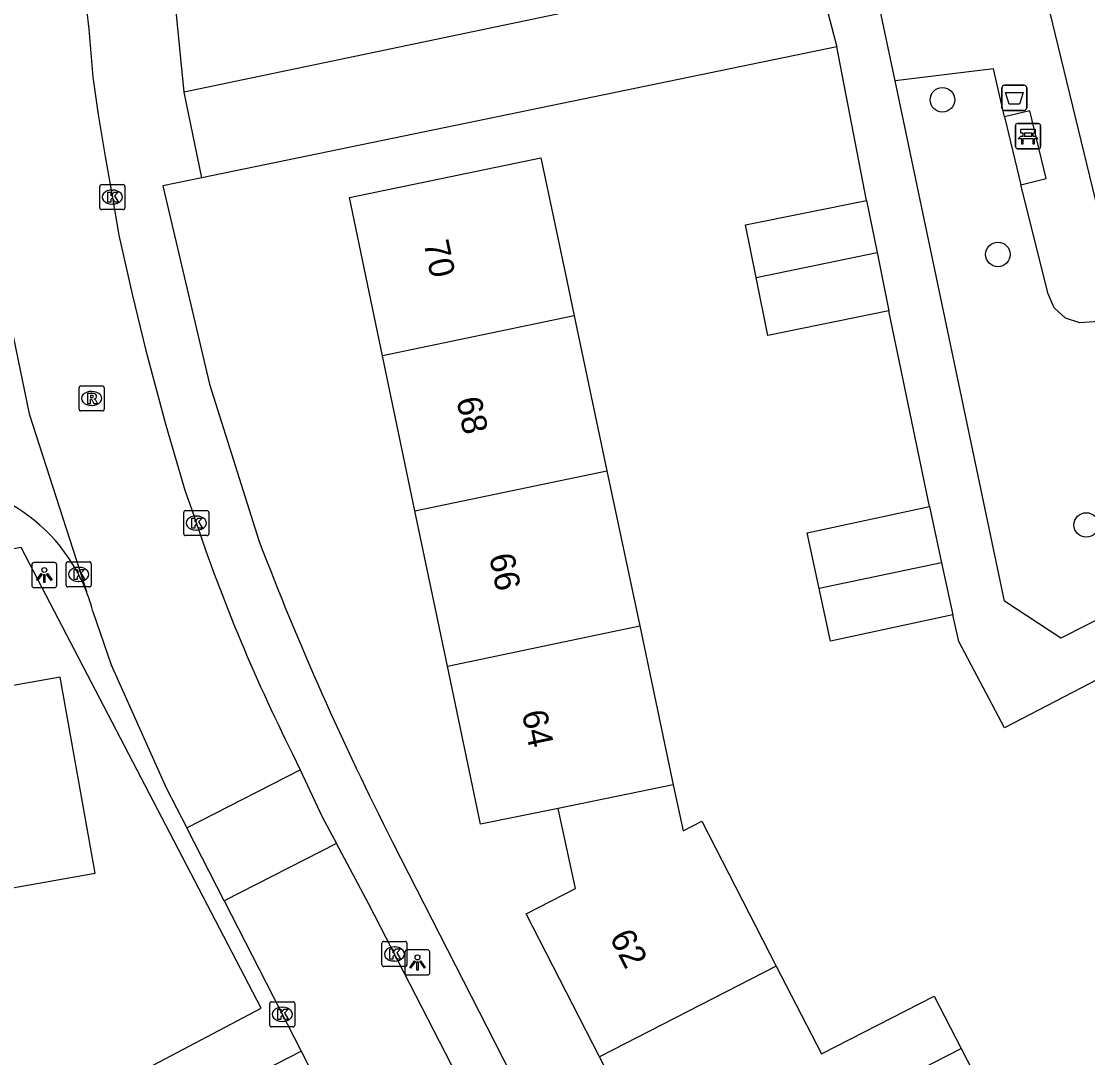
# Model space of a CAD drawing. Extents: x 158461 to 159795, y 387220 to 388672.
# Drawn here: x 159150.7 to 159193.22, y 387884.38 to 387925.7 of the extents above; entities that cross this region are included whole.
import ezdxf

# ---------------------------------------------------------------- set-up
doc = ezdxf.new("R2010")
doc.units = 0
for name, color, linetype in [('IMGEO_Afvalbak', 7, 'Continuous'), ('IMGEO_Bank', 7, 'Continuous'), ('IMGEO_Boom', 7, 'Continuous'), ('IMGEO_Groenvoorziening', 7, 'Continuous'), ('IMGEO_Kolk', 7, 'Continuous'), ('IMGEO_Lichtpunt', 7, 'Continuous'), ('IMGEO_Pand', 7, 'Continuous'), ('IMGEO_Pand_nummerreeks', 7, 'Continuous'), ('IMGEO_Rijbaan_lokaal_open', 7, 'Continuous'), ('IMGEO_Rioolput', 7, 'Continuous'), ('IMGEO_Voetpad_open', 7, 'Continuous')]:
    doc.layers.add(name, color=color, linetype=linetype)

msp = doc.modelspace()

# ---------------------------------------------------------------- linework, layer by layer
at = {"layer": 'IMGEO_Afvalbak'}
for p, q in [((159189.796, 387922.249), (159189.796, 387923.049)), ((159189.796, 387923.049), (159189.796, 387922.249)), ((159189.896, 387923.149), (159190.686, 387923.149)), ((159190.686, 387923.149), (159189.896, 387923.149)), ((159190.786, 387923.049), (159190.786, 387922.249)), ((159190.786, 387922.249), (159190.786, 387923.049)), ((159190.686, 387922.149), (159189.896, 387922.149)), ((159189.896, 387922.149), (159190.686, 387922.149))]:
    msp.add_line(p, q, dxfattribs=at)
msp.add_lwpolyline([(159189.939, 387922.863), (159190.643, 387922.863), (159190.494, 387922.393), (159190.088, 387922.393), (159189.939, 387922.863)], dxfattribs=at)
for centre, start, end in [((159189.896, 387923.049), 90, 180), ((159189.896, 387923.049), 90, 180), ((159190.686, 387923.049), 0, 90), ((159190.686, 387923.049), 360, 90), ((159189.896, 387922.249), 180, 270), ((159189.896, 387922.249), 180, 270), ((159190.686, 387922.249), 270, 0), ((159190.686, 387922.249), 270, 0)]:
    msp.add_arc(centre, 0.1, start, end, dxfattribs=at)
at = {"layer": 'IMGEO_Bank'}
for p, q in [((159190.338, 387920.697), (159190.338, 387921.538)), ((159190.338, 387921.538), (159190.338, 387920.697)), ((159190.413, 387921.622), (159191.254, 387921.622)), ((159191.254, 387921.622), (159190.413, 387921.622)), ((159191.338, 387921.547), (159191.338, 387920.706)), ((159191.338, 387920.706), (159191.338, 387921.547)), ((159190.647, 387921.128), (159190.647, 387921.234)), ((159190.691, 387921.234), (159190.691, 387921.128)), ((159190.979, 387921.24), (159190.697, 387921.24)), ((159190.697, 387921.122), (159190.979, 387921.122)), ((159190.985, 387921.128), (159190.985, 387921.234)), ((159191.029, 387921.234), (159191.029, 387921.128)), ((159191.035, 387921.02), (159190.642, 387921.02)), ((159191.263, 387920.622), (159190.422, 387920.622)), ((159190.422, 387920.622), (159191.263, 387920.622))]:
    msp.add_line(p, q, dxfattribs=at)
for points in [[(159190.585, 387921.02), (159190.443, 387921.02), (159190.555, 387921.122), (159190.641, 387921.122)], [(159190.641, 387921.24), (159190.555, 387921.24), (159190.555, 387921.401), (159191.118, 387921.401), (159191.118, 387921.24), (159191.035, 387921.24)], [(159191.035, 387921.122), (159191.118, 387921.122), (159191.23, 387921.02), (159191.091, 387921.02)], [(159190.635, 387921.013), (159190.635, 387920.806), (159190.592, 387920.806), (159190.592, 387921.013)], [(159191.085, 387921.013), (159191.085, 387920.806), (159191.041, 387920.806), (159191.041, 387921.013)]]:
    msp.add_lwpolyline(points, dxfattribs=at)
for centre, radius, start, end in [((159190.416, 387921.544), 0.0779, 92.4484, 184.2845), ((159190.416, 387921.544), 0.0779, 92.4484, 184.2845), ((159191.26, 387921.544), 0.0779, 2.4484, 94.2845), ((159191.26, 387921.544), 0.0779, 2.4484, 94.2845), ((159190.64, 387921.233), 0.00671, 2.8957, 87.1043), ((159190.64, 387921.129), 0.00671, 272.8957, 357.1043), ((159190.697, 387921.233), 0.00671, 92.8957, 177.1043), ((159190.697, 387921.129), 0.00671, 182.8957, 267.1043), ((159190.979, 387921.233), 0.00671, 2.8957, 87.1043), ((159190.979, 387921.129), 0.00671, 272.8957, 357.1043), ((159191.036, 387921.233), 0.00671, 92.8957, 177.1043), ((159191.036, 387921.129), 0.00671, 182.8957, 267.1043), ((159190.416, 387920.7), 0.0779, 182.4484, 274.2845), ((159190.416, 387920.7), 0.0779, 182.4484, 274.2845), ((159190.585, 387921.013), 0.00671, 2.8957, 87.1043), ((159190.642, 387921.013), 0.00671, 92.8957, 177.1043), ((159191.034, 387921.013), 0.00671, 2.8957, 87.1043), ((159191.091, 387921.013), 0.00671, 92.8957, 177.1043), ((159191.26, 387920.7), 0.0779, 272.4484, 4.2845), ((159191.26, 387920.7), 0.0779, 272.4484, 4.2845)]:
    msp.add_arc(centre, radius, start, end, dxfattribs=at)
at = {"layer": 'IMGEO_Boom'}
for centre in [(159187.425, 387922.57), (159189.638, 387916.405), (159193.159, 387905.619)]:
    msp.add_circle(centre, 0.489, dxfattribs=at)
at = {"layer": 'IMGEO_Groenvoorziening'}
for points in [[(159206.203, 387929.607), (159191.693, 387926.088), (159194.08, 387916.245), (159208.541, 387919.752), (159206.203, 387929.607)], [(159189.899, 387921.887), (159189.467, 387923.801), (159185.537, 387923.326)], [(159211.851, 387914.973), (159209.119, 387915.028), (159207.647, 387913.997), (159206.483, 387913.38), (159205.261, 387912.888), (159203.994, 387912.527), (159202.696, 387912.3), (159201.382, 387912.211), (159200.066, 387912.259), (159198.762, 387912.444), (159197.484, 387912.764), (159196.247, 387913.217), (159195.064, 387913.796), (159193.477, 387913.72), (159192.904, 387913.672), (159192.327, 387913.866), (159191.878, 387914.278), (159191.636, 387914.837), (159190.556, 387919.186)]]:
    msp.add_lwpolyline(points, dxfattribs=at)
at = {"layer": 'IMGEO_Kolk'}
for p, q in [((159153.83, 387918.267), (159153.83, 387919.119)), ((159153.905, 387919.193), (159154.757, 387919.193)), ((159154.831, 387919.119), (159154.831, 387918.267)), ((159154.318, 387918.973), (159154.343, 387918.973)), ((159154.757, 387918.193), (159153.905, 387918.193)), ((159154.341, 387918.413), (159154.316, 387918.413)), ((159157.175, 387905.268), (159157.175, 387906.12)), ((159157.25, 387906.194), (159158.102, 387906.194)), ((159157.663, 387905.974), (159157.688, 387905.974)), ((159158.176, 387906.12), (159158.176, 387905.268)), ((159157.686, 387905.414), (159157.661, 387905.414)), ((159158.102, 387905.194), (159157.25, 387905.194)), ((159152.559, 387904.15), (159153.411, 387904.15)), ((159152.484, 387903.224), (159152.484, 387904.076)), ((159152.972, 387903.93), (159152.997, 387903.93)), ((159153.485, 387904.076), (159153.485, 387903.224)), ((159152.995, 387903.37), (159152.97, 387903.37)), ((159153.411, 387903.15), (159152.559, 387903.15)), ((159165.075, 387888.088), (159165.075, 387888.94)), ((159165.15, 387889.014), (159166.002, 387889.014)), ((159166.076, 387888.94), (159166.076, 387888.088)), ((159165.563, 387888.794), (159165.588, 387888.794)), ((159166.002, 387888.014), (159165.15, 387888.014)), ((159165.586, 387888.234), (159165.561, 387888.234)), ((159160.605, 387885.682), (159160.605, 387886.534)), ((159160.68, 387886.608), (159161.532, 387886.608)), ((159161.093, 387886.388), (159161.118, 387886.388)), ((159161.606, 387886.534), (159161.606, 387885.682)), ((159161.116, 387885.828), (159161.091, 387885.828)), ((159161.532, 387885.608), (159160.68, 387885.608))]:
    msp.add_line(p, q, dxfattribs=at)
for points in [[(159153.83, 387918.267), (159153.83, 387919.119)], [(159153.905, 387919.193), (159154.757, 387919.193)], [(159154.831, 387919.119), (159154.831, 387918.267)], [(159154.151, 387918.893), (159154.274, 387918.893), (159154.274, 387918.742), (159154.404, 387918.893), (159154.568, 387918.893), (159154.422, 387918.742), (159154.575, 387918.493), (159154.423, 387918.493), (159154.338, 387918.657), (159154.274, 387918.59), (159154.274, 387918.493), (159154.151, 387918.493), (159154.151, 387918.893)], [(159154.757, 387918.193), (159153.905, 387918.193)], [(159157.175, 387905.268), (159157.175, 387906.12)], [(159157.25, 387906.194), (159158.102, 387906.194)], [(159157.496, 387905.894), (159157.619, 387905.894), (159157.619, 387905.743), (159157.749, 387905.894), (159157.913, 387905.894), (159157.767, 387905.743), (159157.92, 387905.494), (159157.768, 387905.494), (159157.683, 387905.658), (159157.619, 387905.591), (159157.619, 387905.494), (159157.496, 387905.494), (159157.496, 387905.894)], [(159158.176, 387906.12), (159158.176, 387905.268)], [(159158.102, 387905.194), (159157.25, 387905.194)], [(159152.559, 387904.15), (159153.411, 387904.15)], [(159152.484, 387903.224), (159152.484, 387904.076)], [(159152.805, 387903.85), (159152.928, 387903.85), (159152.928, 387903.699), (159153.058, 387903.85), (159153.222, 387903.85), (159153.076, 387903.699), (159153.229, 387903.45), (159153.077, 387903.45), (159152.992, 387903.614), (159152.928, 387903.547), (159152.928, 387903.45), (159152.805, 387903.45), (159152.805, 387903.85)], [(159153.485, 387904.076), (159153.485, 387903.224)], [(159153.411, 387903.15), (159152.559, 387903.15)], [(159165.075, 387888.088), (159165.075, 387888.94)], [(159165.15, 387889.014), (159166.002, 387889.014)], [(159166.076, 387888.94), (159166.076, 387888.088)], [(159165.396, 387888.714), (159165.519, 387888.714), (159165.519, 387888.563), (159165.649, 387888.714), (159165.813, 387888.714), (159165.667, 387888.563), (159165.82, 387888.314), (159165.668, 387888.314), (159165.583, 387888.478), (159165.519, 387888.411), (159165.519, 387888.314), (159165.396, 387888.314), (159165.396, 387888.714)], [(159166.002, 387888.014), (159165.15, 387888.014)], [(159160.605, 387885.682), (159160.605, 387886.534)], [(159160.68, 387886.608), (159161.532, 387886.608)], [(159160.926, 387886.308), (159161.049, 387886.308), (159161.049, 387886.157), (159161.179, 387886.308), (159161.343, 387886.308), (159161.197, 387886.157), (159161.35, 387885.908), (159161.198, 387885.908), (159161.113, 387886.072), (159161.049, 387886.005), (159161.049, 387885.908), (159160.926, 387885.908), (159160.926, 387886.308)], [(159161.606, 387886.534), (159161.606, 387885.682)], [(159161.532, 387885.608), (159160.68, 387885.608)]]:
    msp.add_lwpolyline(points, dxfattribs=at)
for centre, start, end in [((159153.907, 387919.117), 91.552, 178.448), ((159153.907, 387919.117), 91.552, 178.448), ((159154.755, 387919.117), 1.552, 88.448), ((159154.755, 387919.117), 1.552, 88.448), ((159153.907, 387918.269), 181.552, 268.448), ((159153.907, 387918.269), 181.552, 268.448), ((159154.755, 387918.269), 271.552, 358.448), ((159154.755, 387918.269), 271.552, 358.448), ((159157.252, 387906.118), 91.552, 178.448), ((159157.252, 387906.118), 91.552, 178.448), ((159158.1, 387906.118), 1.552, 88.448), ((159158.1, 387906.118), 1.552, 88.448), ((159157.252, 387905.27), 181.552, 268.448), ((159157.252, 387905.27), 181.552, 268.448), ((159158.1, 387905.27), 271.552, 358.448), ((159158.1, 387905.27), 271.552, 358.448), ((159152.561, 387904.074), 91.552, 178.448), ((159152.561, 387904.074), 91.552, 178.448), ((159153.409, 387904.074), 1.552, 88.448), ((159153.409, 387904.074), 1.552, 88.448), ((159152.561, 387903.226), 181.552, 268.448), ((159152.561, 387903.226), 181.552, 268.448), ((159153.409, 387903.226), 271.552, 358.448), ((159153.409, 387903.226), 271.552, 358.448), ((159165.152, 387888.938), 91.552, 178.448), ((159165.152, 387888.938), 91.552, 178.448), ((159166, 387888.938), 1.552, 88.448), ((159166, 387888.938), 1.552, 88.448), ((159165.152, 387888.09), 181.552, 268.448), ((159165.152, 387888.09), 181.552, 268.448), ((159166, 387888.09), 271.552, 358.448), ((159166, 387888.09), 271.552, 358.448), ((159160.682, 387886.532), 91.552, 178.448), ((159160.682, 387886.532), 91.552, 178.448), ((159161.53, 387886.532), 1.552, 88.448), ((159161.53, 387886.532), 1.552, 88.448), ((159160.682, 387885.684), 181.552, 268.448), ((159160.682, 387885.684), 181.552, 268.448), ((159161.53, 387885.684), 271.552, 358.448), ((159161.53, 387885.684), 271.552, 358.448)]:
    msp.add_arc(centre, 0.0765, start, end, dxfattribs=at)
for centre, major_axis, ratio, start_param, end_param in [((159154.317, 387918.693), (-0.387, 0.002), 0.722429, 4.712389, 7.853982), ((159154.342, 387918.693), (-0.39, 0.002), 0.717154, 1.570796, 4.712389), ((159157.662, 387905.694), (-0.387, 0.002), 0.722429, 4.712389, 7.853982), ((159157.687, 387905.694), (-0.39, 0.002), 0.717154, 1.570796, 4.712389), ((159152.971, 387903.65), (-0.387, 0.002), 0.722429, 4.712389, 7.853982), ((159152.996, 387903.65), (-0.39, 0.002), 0.717154, 1.570796, 4.712389), ((159165.562, 387888.514), (-0.387, 0.002), 0.722429, 4.712389, 7.853982), ((159165.587, 387888.514), (-0.39, 0.002), 0.717154, 1.570796, 4.712389), ((159161.092, 387886.108), (-0.387, 0.002), 0.722429, 4.712389, 7.853982), ((159161.117, 387886.108), (-0.39, 0.002), 0.717154, 1.570796, 4.712389)]:
    msp.add_ellipse(centre, major_axis=major_axis, ratio=ratio, start_param=start_param, end_param=end_param, dxfattribs=at)
at = {"layer": 'IMGEO_Lichtpunt'}
for p, q in [((159152.02, 387904.121), (159151.212, 387904.121)), ((159152.02, 387904.121), (159151.212, 387904.121)), ((159151.118, 387904.026), (159151.118, 387903.219)), ((159151.118, 387904.026), (159151.118, 387903.219)), ((159152.114, 387903.219), (159152.114, 387904.026)), ((159152.114, 387903.219), (159152.114, 387904.026)), ((159151.212, 387903.125), (159152.02, 387903.125)), ((159151.212, 387903.125), (159152.02, 387903.125)), ((159165.997, 387888.579), (159165.997, 387887.772)), ((159165.997, 387888.579), (159165.997, 387887.772)), ((159166.899, 387888.674), (159166.091, 387888.674)), ((159166.899, 387888.674), (159166.091, 387888.674)), ((159166.993, 387887.772), (159166.993, 387888.579)), ((159166.993, 387887.772), (159166.993, 387888.579)), ((159166.091, 387887.678), (159166.899, 387887.678)), ((159166.091, 387887.678), (159166.899, 387887.678))]:
    msp.add_line(p, q, dxfattribs=at)
for points in [[(159151.492, 387903.69), (159151.531, 387903.662), (159151.343, 387903.4), (159151.305, 387903.427), (159151.492, 387903.69)], [(159151.704, 387903.662), (159151.742, 387903.689), (159151.929, 387903.427), (159151.89, 387903.399), (159151.704, 387903.662)], [(159151.594, 387903.642), (159151.641, 387903.642), (159151.641, 387903.32), (159151.594, 387903.32), (159151.594, 387903.642)], [(159166.371, 387888.243), (159166.41, 387888.215), (159166.222, 387887.953), (159166.184, 387887.98), (159166.371, 387888.243)], [(159166.473, 387888.195), (159166.52, 387888.195), (159166.52, 387887.873), (159166.473, 387887.873), (159166.473, 387888.195)], [(159166.583, 387888.215), (159166.621, 387888.242), (159166.808, 387887.98), (159166.769, 387887.952), (159166.583, 387888.215)]]:
    msp.add_lwpolyline(points, dxfattribs=at)
for centre in [(159151.617, 387903.824), (159166.496, 387888.377)]:
    msp.add_circle(centre, 0.0994, dxfattribs=at)
for centre, start, end in [((159151.212, 387904.026), 90, 180), ((159151.212, 387904.026), 90, 180), ((159152.02, 387904.026), 0, 90), ((159152.02, 387904.026), 0, 90), ((159151.212, 387903.219), 180, 270), ((159151.212, 387903.219), 180, 270), ((159152.02, 387903.219), 270, 0), ((159152.02, 387903.219), 270, 360), ((159166.091, 387888.579), 90, 180), ((159166.091, 387888.579), 90, 180), ((159166.899, 387888.579), 0, 90), ((159166.899, 387888.579), 0, 90), ((159166.091, 387887.772), 180, 270), ((159166.091, 387887.772), 180, 270), ((159166.899, 387887.772), 270, 0), ((159166.899, 387887.772), 270, 360)]:
    msp.add_arc(centre, 0.0946, start, end, dxfattribs=at)
at = {"layer": 'IMGEO_Pand'}
for points in [[(159165.103, 387912.368), (159163.785, 387918.674), (159171.413, 387920.263), (159172.446, 387915.371), (159172.743, 387913.964)], [(159180.001, 387915.48), (159179.575, 387917.586), (159184.403, 387918.562)], [(159184.403, 387918.562), (159184.822, 387916.487)], [(159180.001, 387915.48), (159184.822, 387916.487)], [(159184.822, 387916.487), (159185.294, 387914.154)], [(159185.294, 387914.154), (159180.466, 387913.178), (159180.001, 387915.48)], [(159172.743, 387913.964), (159165.103, 387912.368)], [(159172.743, 387913.964), (159174.049, 387907.78)], [(159166.396, 387906.18), (159165.103, 387912.368)], [(159166.396, 387906.18), (159174.049, 387907.78)], [(159174.049, 387907.78), (159175.356, 387901.594)], [(159182.507, 387903.089), (159182.029, 387905.301), (159186.908, 387906.355)], [(159186.908, 387906.355), (159187.393, 387904.111)], [(159167.689, 387899.991), (159166.396, 387906.18)], [(159187.393, 387904.111), (159182.507, 387903.089)], [(159187.393, 387904.111), (159187.842, 387902.035)], [(159147.35, 387890.622), (159153.643, 387891.74), (159152.255, 387899.556), (159148.428, 387898.876), (159147.694, 387903.008), (159145.229, 387902.57)], [(159187.842, 387902.035), (159182.962, 387900.981), (159182.507, 387903.089)], [(159167.689, 387899.991), (159175.356, 387901.594)], [(159175.356, 387901.594), (159176.695, 387895.255)], [(159172.102, 387894.32), (159169.006, 387893.691), (159167.689, 387899.991)], [(159176.695, 387895.255), (159172.102, 387894.32)], [(159176.695, 387895.255), (159177.083, 387893.419), (159177.837, 387893.807), (159180.801, 387888.031)], [(159173.751, 387884.411), (159170.825, 387890.111), (159172.789, 387891.119), (159172.102, 387894.32)], [(159180.801, 387888.031), (159173.751, 387884.411)], [(159180.801, 387888.031), (159182.6, 387884.527), (159187.102, 387886.838), (159188.174, 387884.75)], [(159176.621, 387878.819), (159188.174, 387884.75)], [(159188.174, 387884.75), (159189.147, 387882.854), (159184.682, 387880.563), (159186.58, 387876.865)], [(159176.621, 387878.819), (159173.751, 387884.411)]]:
    msp.add_lwpolyline(points, dxfattribs=at)
at = {"layer": 'IMGEO_Rijbaan_lokaal_open'}
for points in [[(159153.303, 387926.183), (159153.391, 387925.383), (159153.548, 387923.474), (159153.765, 387921.985), (159154.043, 387920.307), (159154.31, 387918.828), (159154.588, 387917.179), (159155.124, 387914.821), (159155.671, 387912.572), (159156.466, 387909.603), (159157.222, 387907.005), (159157.5, 387906.226)], [(159149.393, 387917.852), (159151.007, 387910.048), (159153.293, 387902.972)], [(159155.484, 387883.835), (159160.266, 387886.356), (159150.699, 387904.721), (159121.698, 387899.706)], [(159153.552, 387902.173), (159154.278, 387900.049), (159156.48, 387895.139), (159157.295, 387893.547)], [(159161.515, 387896.493), (159161.813, 387895.86)], [(159157.295, 387893.547), (159161.813, 387895.86)], [(159161.813, 387895.86), (159162.696, 387893.98), (159163.263, 387892.918)], [(159158.79, 387890.628), (159157.295, 387893.547)], [(159163.263, 387892.918), (159158.79, 387890.628)], [(159179.886, 387860.695), (159164.538, 387890.533), (159163.263, 387892.918)], [(159158.79, 387890.628), (159161.853, 387884.646)], [(159170.45, 387867.911), (159165.692, 387865.455), (159157.095, 387882.191), (159161.853, 387884.646)], [(159161.853, 387884.646), (159166.778, 387875.029), (159170.45, 387867.911)]]:
    msp.add_lwpolyline(points, dxfattribs=at)
for centre, radius, start, end in [((159146.899, 387900.461), 6.87, 21.4432, 99.8039), ((159225.328, 387928.511), 71.395, 198.1883, 206.64537), ((159146.961, 387900.478), 6.806, 14.4225, 21.4983)]:
    msp.add_arc(centre, radius, start, end, dxfattribs=at)
at = {"layer": 'IMGEO_Rioolput'}
for p, q in [((159153.002, 387910.238), (159153.002, 387911.09)), ((159153.077, 387911.164), (159153.929, 387911.164)), ((159153.49, 387910.944), (159153.515, 387910.944)), ((159154.003, 387911.09), (159154.003, 387910.238)), ((159153.929, 387910.164), (159153.077, 387910.164)), ((159153.513, 387910.384), (159153.488, 387910.384))]:
    msp.add_line(p, q, dxfattribs=at)
for points in [[(159153.002, 387910.238), (159153.002, 387911.09)], [(159153.077, 387911.164), (159153.929, 387911.164)], [(159154.003, 387911.09), (159154.003, 387910.238)], [(159153.591, 387910.862), (159153.339, 387910.864), (159153.339, 387910.464)], [(159153.339, 387910.464), (159153.463, 387910.464), (159153.463, 387910.626), (159153.474, 387910.626)], [(159153.517, 387910.783), (159153.463, 387910.783), (159153.463, 387910.702)], [(159153.463, 387910.702), (159153.515, 387910.702)], [(159153.521, 387910.597), (159153.592, 387910.464), (159153.732, 387910.464), (159153.667, 387910.59)], [(159153.929, 387910.164), (159153.077, 387910.164)]]:
    msp.add_lwpolyline(points, dxfattribs=at)
for centre, radius, start, end in [((159153.079, 387911.088), 0.0765, 91.552, 178.448), ((159153.079, 387911.088), 0.0765, 91.552, 178.448), ((159153.927, 387911.088), 0.0765, 1.552, 88.448), ((159153.927, 387911.088), 0.0765, 1.552, 88.448), ((159153.473, 387910.573), 0.0533, 26.0293, 88.6989), ((159153.499, 387910.891), 0.19, 274.7715, 282.9687), ((159153.523, 387910.687), 0.0964, 77.0061, 93.1865), ((159153.537, 387910.744), 0.0378, 276.6634, 79.6772), ((159153.59, 387910.752), 0.109, 350.3612, 89.416), ((159153.588, 387910.752), 0.112, 277.5842, 350.9817), ((159153.572, 387910.537), 0.108, 29.5134, 73.7905), ((159153.079, 387910.24), 0.0765, 181.552, 268.448), ((159153.079, 387910.24), 0.0765, 181.552, 268.448), ((159153.927, 387910.24), 0.0765, 271.552, 358.448), ((159153.927, 387910.24), 0.0765, 271.552, 358.448)]:
    msp.add_arc(centre, radius, start, end, dxfattribs=at)
for centre, major_axis, ratio, start_param, end_param in [((159153.489, 387910.664), (-0.387, 0.002), 0.722429, 4.712389, 7.853982), ((159153.514, 387910.664), (-0.39, 0.002), 0.717154, 1.570796, 4.712389)]:
    msp.add_ellipse(centre, major_axis=major_axis, ratio=ratio, start_param=start_param, end_param=end_param, dxfattribs=at)
at = {"layer": 'IMGEO_Voetpad_open'}
for points in [[(159157.194, 387922.869), (159153.194, 387963.297), (159152.924, 387968.302), (159152.847, 387969.739)], [(159185.537, 387923.326), (159184.535, 387928.096), (159183.999, 387933.425)], [(159182.317, 387928.139), (159157.194, 387922.869)], [(159182.317, 387928.139), (159183.22, 387924.688)], [(159183.22, 387924.688), (159157.899, 387919.457)], [(159184.403, 387918.562), (159183.22, 387924.688)], [(159211.851, 387914.973), (159212.694, 387911.511), (159192.141, 387901.1), (159189.895, 387902.582), (159185.537, 387923.326)], [(159157.899, 387919.457), (159157.194, 387922.869)], [(159190.556, 387919.186), (159191.566, 387919.432), (159190.91, 387922.133), (159189.899, 387921.887)], [(159189.899, 387921.887), (159190.556, 387919.186)], [(159157.899, 387919.457), (159156.344, 387919.136), (159158.204, 387911.239), (159160.185, 387904.963)], [(159186.908, 387906.355), (159185.294, 387914.154)], [(159194.958, 387900.168), (159189.905, 387897.525), (159188.084, 387900.973), (159187.842, 387902.035)], [(159165.502, 387892.978), (159181.495, 387861.65)]]:
    msp.add_lwpolyline(points, dxfattribs=at)
msp.add_arc((159276.865, 387949.555), 124.911, 200.91543, 206.93235, dxfattribs=at)

# ---------------------------------------------------------------- texts
at = {"layer": 'IMGEO_Pand_nummerreeks'}
for s, rotation, p in [('70', 281.8039, (159166.735, 387916.872)), ('68', 281.8039, (159168.041, 387910.627)), ('66', 281.8039, (159169.346, 387904.384)), ('64', 281.8039, (159170.651, 387898.138)), ('62', 297.1702, (159174.135, 387889.181))]:
    msp.add_text(s, height=1, rotation=rotation, dxfattribs=at).set_placement(p)

doc.saveas('drawing.dxf')
